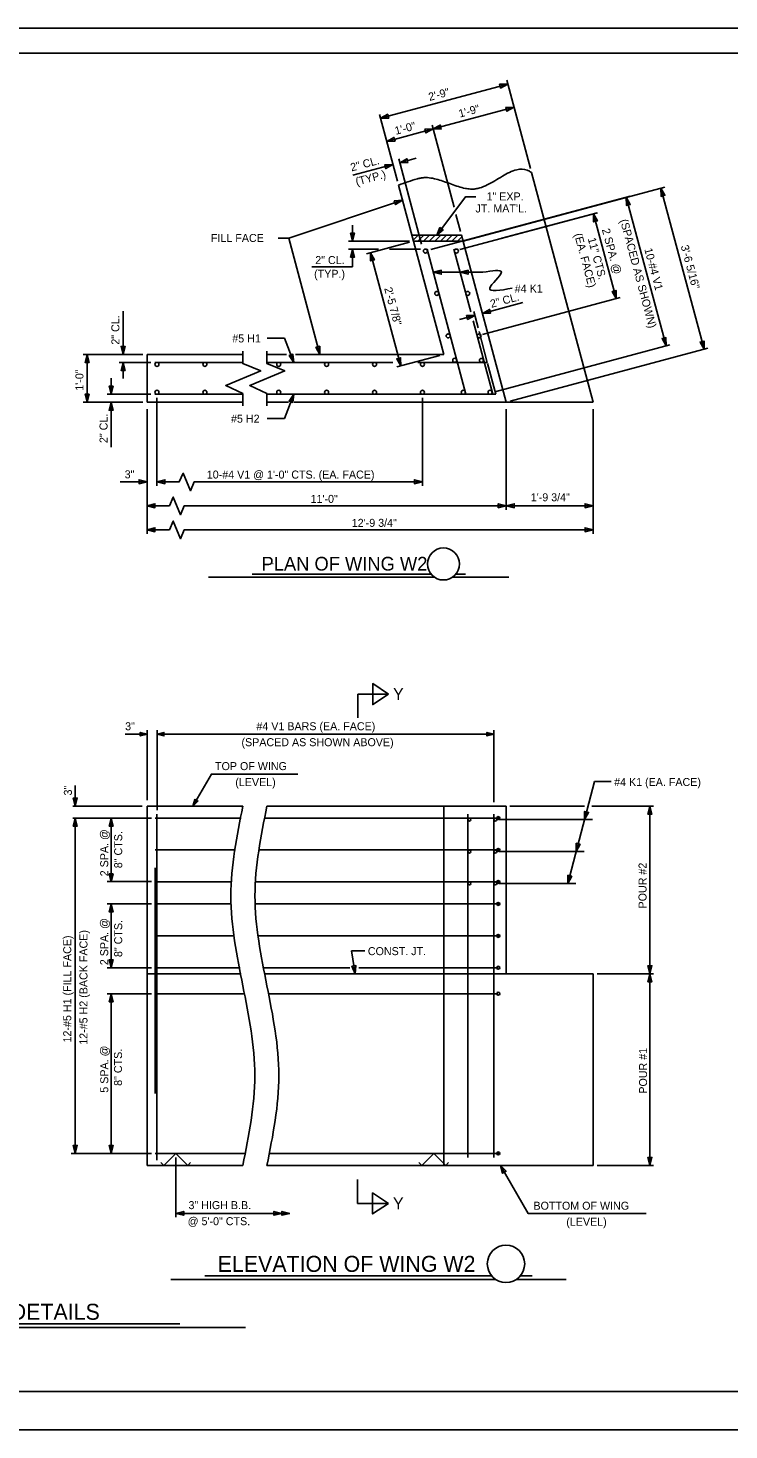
# Model space of a CAD drawing. Extents: x -41 to 191, y -168 to 6.
# Drawn here: x 18.42 to 33.05, y -98.82 to -69.56 of the extents above; entities that cross this region are included whole.
import ezdxf

# ---------------------------------------------------------------- set-up
doc = ezdxf.new("R2010")
doc.units = 0
for name, color, linetype in [('Arrowhead Terminators CELL', 7, 'Continuous'), ('Beam Bolsters CELL', 7, 'Continuous'), ('Default', 7, 'Continuous'), ('Dimension Lines', 7, 'Continuous'), ('Mis Object Lines', 7, 'Continuous'), ('Mis Object Lines Hidden', 7, 'Continuous'), ('Plan Sheet CELL', 7, 'Continuous'), ('Plot Shape CELL', 7, 'Continuous'), ('Rebar K Bar Lines', 7, 'Continuous'), ('Rebar Lines', 7, 'Continuous'), ('Sub End Bent Cap Lines', 7, 'Continuous'), ('Sub End Bent Cap Lines CELL', 7, 'Continuous'), ('Subtitle Text', 7, 'Continuous'), ('Text', 7, 'Continuous'), ('Title Text', 7, 'Continuous'), ('User Information Notes CELL', 7, 'Continuous')]:
    doc.layers.add(name, color=color, linetype=linetype)

# ---------------------------------------------------------------- blocks, each defined once
blk = doc.blocks.new('3 HIGH BEAM BOLSTER')
at = {"layer": 'Default'}
blk.add_lwpolyline([(-0.31, -0.192), (-0.251, -0.251), (0, 0), (0.251, -0.251), (0.31, -0.192)], dxfattribs=at)
blk = doc.blocks.new('SECSYM')
at = {"layer": 'Arrowhead Terminators CELL'}
blk.add_lwpolyline([(0, 0), (-2.48, 1.65), (-2.48, -1.65)], close=True, dxfattribs=at)
blk = doc.blocks.new('AH')
at = {"layer": 'Sub End Bent Cap Lines CELL'}
blk.add_lwpolyline([(0, 0), (-1.25, 0.31), (-1.25, -0.31)], close=True, dxfattribs=at)

msp = doc.modelspace()

# ---------------------------------------------------------------- linework, layer by layer
at = {"layer": 'Arrowhead Terminators CELL'}
for points in [[(28.436, -70.734), (28.265, -70.737), (28.286, -70.817)], [(25.78, -71.446), (25.951, -71.443), (25.93, -71.363)], [(28.566, -71.217), (28.394, -71.22), (28.416, -71.3)], [(26.875, -71.67), (26.704, -71.673), (26.725, -71.753)], [(26.875, -71.67), (27.047, -71.667), (27.025, -71.587)], [(25.909, -71.929), (26.081, -71.926), (26.059, -71.846)], [(26.039, -72.412), (25.867, -72.415), (25.889, -72.495)], [(26.18, -72.374), (26.352, -72.371), (26.33, -72.291)], [(30.908, -73.094), (30.911, -73.265), (30.991, -73.244)], [(31.633, -72.904), (31.636, -73.076), (31.716, -73.054)], [(26.238, -73.157), (26.067, -73.17), (26.094, -73.249)], [(30.224, -73.439), (30.227, -73.61), (30.307, -73.589)], [(26.951, -73.886), (27.085, -73.778), (27.018, -73.728)], [(25.195, -74.011), (25.237, -73.845), (25.153, -73.845)], [(25.195, -74.178), (25.153, -74.344), (25.237, -74.344)], [(25.568, -74.252), (25.571, -74.423), (25.652, -74.402)], [(26.879, -74.661), (27.045, -74.702), (27.045, -74.619)], [(27.439, -74.661), (27.606, -74.702), (27.606, -74.619)], [(30.698, -75.21), (30.695, -75.039), (30.615, -75.06)], [(27.907, -75.519), (28.078, -75.516), (28.056, -75.436)], [(27.746, -75.562), (27.574, -75.565), (27.596, -75.645)], [(31.739, -76.196), (31.736, -76.025), (31.656, -76.046)], [(24.514, -76.374), (24.511, -76.203), (24.431, -76.224)], [(32.535, -76.267), (32.532, -76.096), (32.451, -76.118)], [(23.971, -76.541), (23.95, -76.371), (23.873, -76.4)], [(26.202, -76.615), (26.199, -76.444), (26.119, -76.465)], [(23.971, -77.208), (23.95, -77.378), (23.873, -77.348)], [(20.904, -79.033), (20.737, -78.992), (20.737, -79.075)], [(21.112, -79.033), (21.279, -79.075), (21.279, -78.992)], [(26.654, -79.033), (26.487, -78.992), (26.487, -79.075)], [(20.904, -79.533), (21.07, -79.575), (21.07, -79.492)], [(28.404, -79.533), (28.237, -79.492), (28.237, -79.575)], [(28.404, -79.533), (28.57, -79.575), (28.57, -79.492)], [(30.215, -79.533), (30.049, -79.492), (30.049, -79.575)], [(20.904, -80.033), (21.07, -80.075), (21.07, -79.992)], [(30.215, -80.033), (30.049, -79.992), (30.049, -80.075)], [(20.905, -84.302), (20.763, -84.337), (20.763, -84.266)], [(21.114, -84.302), (21.256, -84.266), (21.256, -84.337)], [(28.142, -84.302), (28, -84.337), (28, -84.266)], [(19.405, -85.802), (19.447, -85.635), (19.364, -85.635)], [(21.862, -85.802), (21.965, -85.697), (21.904, -85.661)], [(30.038, -86.083), (30.04, -85.912), (30.121, -85.933)], [(31.404, -85.802), (31.362, -85.968), (31.445, -85.968)], [(19.405, -86.052), (19.364, -86.218), (19.447, -86.218)], [(20.155, -86.052), (20.114, -86.218), (20.197, -86.218)], [(29.863, -86.75), (29.865, -86.578), (29.946, -86.599)], [(20.155, -87.379), (20.197, -87.213), (20.114, -87.213)], [(29.688, -87.416), (29.69, -87.245), (29.771, -87.266)], [(20.155, -87.843), (20.114, -88.01), (20.197, -88.01)], [(20.155, -89.177), (20.197, -89.01), (20.114, -89.01)], [(25.252, -89.302), (25.183, -89.145), (25.265, -89.131)], [(31.404, -89.302), (31.445, -89.135), (31.362, -89.135)], [(31.404, -89.302), (31.362, -89.468), (31.445, -89.468)], [(20.155, -89.718), (20.114, -89.885), (20.197, -89.885)], [(19.405, -93.052), (19.447, -92.885), (19.364, -92.885)], [(20.155, -93.052), (20.197, -92.885), (20.114, -92.885)], [(28.28, -93.302), (28.399, -93.425), (28.327, -93.466)], [(31.404, -93.302), (31.445, -93.135), (31.362, -93.135)], [(21.505, -94.302), (21.671, -94.26), (21.671, -94.343)], [(23.72, -94.302), (23.554, -94.26), (23.554, -94.343)], [(23.886, -94.302), (23.72, -94.26), (23.72, -94.343)]]:
    msp.add_lwpolyline(points, close=True, dxfattribs=at)
at = {"layer": 'Beam Bolsters CELL'}
msp.add_lwpolyline([(21.814, -93.243), (21.755, -93.302), (21.505, -93.052), (21.254, -93.302), (21.195, -93.243)], dxfattribs=at)
at = {"layer": 'Default'}
for points in [[(22.904, -77.449), (22.904, -77.191), (22.546, -77.027), (23.279, -76.721), (22.904, -76.566), (22.904, -76.304)], [(23.406, -77.449), (23.406, -77.191), (23.048, -77.027), (23.781, -76.721), (23.406, -76.566), (23.406, -76.304)], [(21.449, -79.033), (21.578, -79.033), (21.66, -78.854), (21.813, -79.221), (21.891, -79.033), (22.022, -79.033)], [(21.241, -79.533), (21.37, -79.533), (21.452, -79.354), (21.605, -79.721), (21.682, -79.533), (21.813, -79.533)], [(21.241, -80.033), (21.37, -80.033), (21.452, -79.854), (21.605, -80.221), (21.682, -80.033), (21.813, -80.033)]]:
    msp.add_lwpolyline(points, dxfattribs=at)
at = {"layer": 'Dimension Lines'}
for p, q in [((25.78, -71.446), (28.436, -70.734)), ((28.908, -72.496), (28.415, -70.654)), ((26.132, -72.762), (25.758, -71.365)), ((26.875, -71.67), (28.566, -71.217)), ((25.909, -71.929), (26.875, -71.67)), ((27.313, -73.304), (26.854, -71.59)), ((25.198, -72.637), (26.039, -72.412)), ((26.636, -74.075), (26.159, -72.293)), ((26.522, -72.282), (26.18, -72.374)), ((26.831, -74.186), (30.988, -73.072)), ((27.503, -74.011), (31.714, -72.883)), ((30.908, -73.094), (31.739, -76.196)), ((31.633, -72.904), (32.535, -76.267)), ((27.431, -74.187), (30.307, -73.417)), ((28.311, -73.952), (30.304, -73.418)), ((30.224, -73.439), (30.698, -75.21)), ((25.195, -73.678), (25.195, -74.011)), ((27.449, -73.811), (27.353, -73.454)), ((26.384, -74.011), (25.112, -74.011)), ((26.462, -73.991), (26.567, -73.886)), ((26.56, -74.011), (26.685, -73.886)), ((26.678, -74.011), (26.803, -73.886)), ((26.795, -74.011), (26.92, -73.886)), ((26.913, -74.011), (27.038, -73.886)), ((27.031, -74.011), (27.156, -73.886)), ((27.149, -74.011), (27.274, -73.886)), ((27.267, -74.011), (27.392, -73.886)), ((27.385, -74.011), (27.478, -73.918)), ((25.735, -74.178), (25.112, -74.178)), ((25.195, -74.511), (25.195, -74.178)), ((26.387, -74.033), (25.488, -74.273)), ((25.568, -74.252), (26.202, -76.615)), ((26.613, -74.178), (25.966, -74.178)), ((24.344, -74.548), (25.195, -74.548)), ((25.195, -74.548), (25.195, -74.459)), ((29.427, -74.432), (29.427, -74.432)), ((27.439, -74.661), (26.879, -74.661)), ((27.915, -74.661), (27.439, -74.661)), ((27.906, -75.958), (30.779, -75.188)), ((20.404, -75.475), (20.404, -76.374)), ((27.724, -75.482), (27.814, -75.819)), ((27.907, -75.519), (28.748, -75.294)), ((27.746, -75.562), (27.424, -75.648)), ((23.414, -76.035), (23.777, -76.035)), ((23.777, -76.035), (23.971, -76.541)), ((28.162, -77.155), (31.819, -76.175)), ((28.484, -77.353), (32.615, -76.246)), ((20.82, -76.374), (19.57, -76.374)), ((19.654, -76.374), (19.654, -77.374)), ((20.987, -76.541), (20.32, -76.541)), ((20.404, -76.875), (20.404, -76.541)), ((20.82, -76.374), (20.467, -76.374)), ((27.02, -76.396), (26.121, -76.637)), ((20.154, -76.874), (20.154, -77.208)), ((20.987, -77.208), (20.07, -77.208)), ((23.777, -77.714), (23.971, -77.208)), ((20.82, -77.374), (19.57, -77.374)), ((20.154, -78.308), (20.154, -77.374)), ((20.82, -77.374), (20.178, -77.374)), ((20.904, -77.517), (20.904, -80.117)), ((21.112, -77.279), (21.112, -79.118)), ((26.654, -77.279), (26.654, -79.118)), ((28.404, -77.517), (28.404, -79.617)), ((30.215, -77.517), (30.215, -80.117)), ((23.414, -77.714), (23.777, -77.714)), ((20.341, -79.033), (20.904, -79.033)), ((21.449, -79.033), (21.112, -79.033)), ((22.022, -79.033), (26.654, -79.033)), ((21.241, -79.533), (20.904, -79.533)), ((28.404, -79.533), (21.813, -79.533)), ((30.215, -79.533), (28.404, -79.533)), ((21.241, -80.033), (20.904, -80.033)), ((30.215, -80.033), (21.813, -80.033)), ((25.302, -83.463), (25.302, -83.961)), ((25.945, -83.463), (25.302, -83.463)), ((20.905, -85.679), (20.905, -84.218)), ((21.114, -85.885), (21.114, -84.218)), ((28.142, -85.718), (28.142, -84.218)), ((20.447, -84.302), (20.905, -84.302)), ((28.142, -84.302), (21.114, -84.302)), ((19.405, -85.802), (19.405, -85.37)), ((29.688, -87.416), (30.247, -85.287)), ((30.247, -85.287), (30.592, -85.287)), ((20.802, -85.802), (19.357, -85.802)), ((28.476, -85.802), (30.038, -85.802)), ((30.189, -85.802), (31.475, -85.802)), ((31.404, -89.302), (31.404, -85.802)), ((21, -86.052), (19.357, -86.052)), ((19.405, -86.052), (19.405, -93.052)), ((20.155, -87.379), (20.155, -86.052)), ((28.258, -86.083), (30.205, -86.083)), ((28.258, -86.75), (30.03, -86.75)), ((21, -87.379), (20.072, -87.379)), ((28.258, -87.416), (29.855, -87.416)), ((21, -87.843), (20.072, -87.843)), ((20.155, -89.177), (20.155, -87.843)), ((25.252, -89.302), (25.172, -88.825)), ((25.172, -88.825), (25.453, -88.825)), ((21, -89.177), (20.072, -89.177)), ((30.301, -89.302), (31.476, -89.302)), ((31.404, -93.302), (31.404, -89.302)), ((21, -89.718), (20.072, -89.718)), ((20.155, -93.052), (20.155, -89.718)), ((21, -93.052), (19.322, -93.052)), ((21.505, -93.135), (21.505, -94.385)), ((30.301, -93.302), (31.476, -93.302)), ((25.3, -94.094), (25.3, -93.594)), ((25.944, -94.094), (25.3, -94.094)), ((25.379, -94.094), (25.944, -94.094)), ((23.886, -94.302), (21.505, -94.302))]:
    msp.add_line(p, q, dxfattribs=at)
for points in [[(27.77, -73.089), (27.551, -73.089), (26.951, -73.886)], [(26.238, -73.157), (23.864, -73.95), (23.643, -73.95)], [(23.643, -73.95), (23.864, -73.95), (24.514, -76.374)], [(24.055, -85.135), (22.247, -85.135), (21.862, -85.802)], [(31.321, -94.302), (28.858, -94.302), (28.28, -93.302)]]:
    msp.add_lwpolyline(points, dxfattribs=at)
msp.add_lwpolyline([(26.434, -73.886), (26.467, -74.011), (27.503, -74.011), (27.469, -73.886)], close=True, dxfattribs=at)
for points in [[(27.915, -74.661), (28.301, -74.661), (28.059, -74.993), (28.527, -74.993)], [(22.905, -85.802), (22.655, -87.677), (22.905, -89.552), (23.155, -91.427), (22.905, -93.302)], [(23.407, -85.802), (23.157, -87.677), (23.407, -89.552), (23.657, -91.427), (23.407, -93.302)]]:
    msp.add_spline(points, degree=3, dxfattribs=at)
at = {"layer": 'Mis Object Lines'}
for p, q in [((20.905, -85.802), (22.905, -85.802)), ((20.905, -85.802), (20.905, -93.302)), ((23.407, -85.802), (28.404, -85.802)), ((28.404, -89.302), (28.404, -85.802)), ((30.215, -89.302), (28.404, -89.302)), ((30.215, -93.302), (30.215, -89.302)), ((20.905, -93.302), (22.905, -93.302)), ((23.407, -93.302), (30.215, -93.302))]:
    msp.add_line(p, q, dxfattribs=at)
msp.add_spline([(26.154, -72.842), (26.548, -72.711), (26.618, -72.694), (26.688, -72.685), (26.829, -72.693), (27.117, -72.771), (27.406, -72.873), (27.55, -72.91), (27.658, -72.924), (27.693, -72.925), (27.732, -72.924), (27.771, -72.919), (27.849, -72.901), (28.007, -72.837), (28.323, -72.657), (28.626, -72.52), (28.839, -72.527), (28.906, -72.561), (28.93, -72.577)], degree=3, dxfattribs=at)
at = {"layer": 'Mis Object Lines Hidden'}
for p, q in [((27.1, -85.802), (27.1, -93.302)), ((22.868, -89.302), (20.905, -89.302)), ((28.404, -89.302), (23.37, -89.302))]:
    msp.add_line(p, q, dxfattribs=at)
at = {"layer": 'Plan Sheet CELL'}
for p, q in [((1.402, -70.087), (43.962, -70.087)), ((1.402, -98.017), (43.962, -98.017))]:
    msp.add_line(p, q, dxfattribs=at)
at = {"layer": 'Plot Shape CELL'}
msp.add_lwpolyline([(0, -69.563), (43.974, -69.563), (43.974, -98.823), (0, -98.823)], close=True, dxfattribs=at)
at = {"layer": 'Rebar K Bar Lines'}
for p, q in [((27.561, -77.208), (26.749, -74.178)), ((27.661, -75.489), (27.31, -74.178)), ((28.122, -77.208), (27.71, -75.673))]:
    msp.add_line(p, q, dxfattribs=at)
for centre in [(27.633, -86.083), (28.175, -86.083), (27.633, -86.75), (28.175, -86.75), (27.633, -87.416), (28.175, -87.416)]:
    msp.add_circle(centre, 0.0312, dxfattribs=at)
at = {"layer": 'Rebar Lines'}
for p, q in [((28.008, -76.541), (27.835, -75.897)), ((22.904, -76.541), (21.07, -76.541)), ((26.035, -76.541), (23.406, -76.541)), ((28.008, -76.541), (26.556, -76.541)), ((28.186, -77.208), (28.014, -76.564)), ((22.904, -77.208), (21.07, -77.208)), ((28.186, -77.208), (23.406, -77.208)), ((21.112, -85.968), (21.112, -93.189)), ((27.598, -85.968), (27.598, -93.135)), ((28.142, -85.968), (28.142, -93.135)), ((21.072, -86.052), (22.868, -86.052)), ((23.37, -86.052), (28.273, -86.052)), ((21.072, -86.718), (22.752, -86.718)), ((23.254, -86.718), (28.273, -86.718)), ((21.072, -87.385), (22.666, -87.385)), ((23.168, -87.385), (28.273, -87.385)), ((21.072, -87.843), (22.659, -87.843)), ((23.161, -87.843), (28.273, -87.843)), ((21.072, -88.51), (22.732, -88.51)), ((23.234, -88.51), (28.273, -88.51)), ((21.072, -89.177), (22.847, -89.177)), ((23.349, -89.177), (25.135, -89.177)), ((25.324, -89.177), (28.237, -89.177)), ((21.072, -89.718), (22.929, -89.718)), ((23.431, -89.718), (28.237, -89.718)), ((21.072, -93.052), (22.942, -93.052)), ((23.444, -93.052), (28.275, -93.052))]:
    msp.add_line(p, q, dxfattribs=at)
for centre, radius in [((26.716, -74.217), 0.0417), ((27.362, -74.217), 0.0417), ((26.953, -75.102), 0.0417), ((27.599, -75.102), 0.0417), ((27.191, -75.988), 0.0417), ((27.837, -75.988), 0.0417), ((21.112, -76.583), 0.0417), ((22.112, -76.583), 0.0417), ((23.654, -76.583), 0.0417), ((24.654, -76.583), 0.0417), ((25.654, -76.583), 0.0417), ((26.654, -76.583), 0.0417), ((27.327, -76.498), 0.0417), ((27.886, -76.499), 0.0417), ((21.112, -77.166), 0.0417), ((22.112, -77.166), 0.0417), ((23.654, -77.166), 0.0417), ((24.654, -77.166), 0.0417), ((25.654, -77.166), 0.0417), ((26.654, -77.166), 0.0417), ((27.506, -77.165), 0.0417), ((28.065, -77.165), 0.0417), ((28.237, -86.052), 0.0312), ((28.237, -86.718), 0.0312), ((28.237, -87.385), 0.0312), ((28.237, -87.843), 0.0312), ((28.237, -88.51), 0.0312), ((28.237, -89.177), 0.0312), ((28.237, -89.718), 0.0312), ((28.237, -93.052), 0.0312)]:
    msp.add_circle(centre, radius, dxfattribs=at)
at = {"layer": 'Sub End Bent Cap Lines'}
for p, q in [((27.1, -76.374), (26.154, -72.842)), ((30.215, -77.374), (28.93, -72.577)), ((27.503, -74.011), (26.467, -74.011)), ((28.404, -77.374), (27.505, -74.021)), ((20.904, -77.374), (20.904, -76.374)), ((22.904, -76.374), (20.904, -76.374)), ((23.813, -76.374), (23.406, -76.374)), ((27.1, -76.374), (24.002, -76.374)), ((22.904, -77.374), (20.904, -77.374)), ((23.859, -77.374), (23.406, -77.374)), ((30.215, -77.374), (23.977, -77.374))]:
    msp.add_line(p, q, dxfattribs=at)
at = {"layer": 'Title Text'}
for p, q in [((22.191, -81.021), (26.9, -81.021)), ((23.101, -80.958), (26.832, -80.958)), ((27.284, -81.021), (28.459, -81.021)), ((27.351, -80.958), (27.55, -80.958)), ((22.114, -95.607), (28.1, -95.607)), ((28.696, -95.607), (28.945, -95.607)), ((21.402, -95.681), (28.183, -95.681)), ((28.612, -95.681), (29.656, -95.681)), ((14.226, -96.681), (22.963, -96.681)), ((14.89, -96.681), (21.67, -96.681)), ((15.601, -96.607), (21.587, -96.607))]:
    msp.add_line(p, q, dxfattribs=at)
for centre, radius in [((27.092, -80.749), 0.334), ((23.537, -80.743), 0.000000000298), ((28.398, -95.356), 0.39)]:
    msp.add_circle(centre, radius, dxfattribs=at)
at = {"layer": 'User Information Notes CELL'}
msp.add_line((21.072, -87.092), (21.072, -91.802), dxfattribs=at)

# ---------------------------------------------------------------- block references
at = {"layer": 'Arrowhead Terminators CELL', "xscale": 0.1336, "yscale": -0.1336}
for p, rotation in [((20.404, -76.374), -90), ((19.654, -76.374), 90), ((20.404, -76.541), 90), ((19.654, -77.374), -90), ((20.154, -77.208), -90), ((20.154, -77.374), 90)]:
    msp.add_blockref('AH', p, dxfattribs=dict(at, rotation=rotation))
at = {"layer": 'Dimension Lines', "xscale": 0.1331292, "yscale": 0.133130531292}
for p in [(25.945, -83.463), (25.944, -94.094)]:
    msp.add_blockref('SECSYM', p, dxfattribs=at)
at = {"layer": 'Rebar Lines', "yscale": 1.00001}
msp.add_blockref('3 HIGH BEAM BOLSTER', (26.889, -93.052), dxfattribs=at)

# ---------------------------------------------------------------- texts
at = {"layer": 'Subtitle Text'}
for p in [(26.04, -83.586), (26.038, -94.218)]:
    msp.add_text('Y', height=0.25, dxfattribs=at).set_placement(p)
at = {"layer": 'Text'}
for s, height, rotation, p in [('2\'-9"', 0.167, 15, (26.803, -71.086)), ('1\'-9"', 0.167, 15, (27.434, -71.434)), ('1\'-0"', 0.167, 15, (26.1, -71.792)), ('2" CL.', 0.167, 15, (25.175, -72.557)), ('(TYP.)', 0.167, 15, (25.282, -72.854)), ('(SPACED AS SHOWN)', 0.167, 285, (30.777, -73.575)), ('(EA. FACE)', 0.167, 285, (29.82, -73.869)), ('11" CTS.', 0.167, 285, (30.104, -73.959)), ('2 SPA. @', 0.167, 285, (30.398, -73.769)), ('2" CL.', 0.167, 0, (24.416, -74.489)), ('10-#4 V1', 0.167, 285, (31.284, -74.178)), ('3\'-6 5/16"', 0.167, 285, (32.044, -74.115)), ('(TYP.)', 0.167, 360, (24.392, -74.776)), ('2\'-5 7/8"', 0.1667, 285, (25.854, -74.997)), ('2" CL.', 0.167, 15, (28.094, -75.404)), ('2" CL.', 0.167, 90, (20.327, -76.172)), ('1\'-0"', 0.167, 90, (19.577, -77.133)), ('2" CL.', 0.167, 90, (20.08, -78.225)), ('10-#4 V1 @ 1\'-0" CTS. (EA. FACE)', 0.167, 360, (22.152, -78.966)), ('11\'-0"', 0.167, 360, (24.318, -79.474)), ('12\'-9 3/4"', 0.167, 360, (25.178, -79.974)), ('3"', 0.167, 90, (19.336, -85.58)), ('2 SPA. @', 0.167, 90, (20.094, -87.267)), ('8" CTS.', 0.167, 90, (20.386, -87.099)), ('POUR #2', 0.167, 90, (31.332, -87.939)), ('2 SPA. @', 0.167, 90, (20.094, -89.122)), ('8" CTS.', 0.167, 90, (20.386, -88.953)), ('12-#5 H1 (FILL FACE)', 0.167, 90, (19.322, -90.736)), ('12-#5 H2 (BACK FACE)', 0.167, 90, (19.661, -90.784)), ('CONST. JT.', 0.167, 360, (25.514, -88.913)), ('5 SPA. @', 0.167, 90, (20.095, -91.784)), ('8" CTS.', 0.167, 90, (20.382, -91.641)), ('POUR #1', 0.167, 90, (31.343, -91.804))]:
    msp.add_text(s, height=height, rotation=rotation, dxfattribs=at).set_placement(p)
for s, height, p in [('1" EXP.', 0.167, (27.992, -73.161)), ("JT. MAT'L.", 0.167, (27.762, -73.412)), ('FILL FACE', 0.167, (22.238, -74.028)), ('#4 K1', 0.167, (28.581, -75.083)), ('#5 H1', 0.167, (22.684, -76.125)), ('#5 H2', 0.167, (22.658, -77.8)), ('3"', 0.1667, (20.437, -78.961)), ('1\'-9 3/4"', 0.1667, (28.915, -79.44)), ('3"', 0.167, (20.447, -84.219)), ('#4 V1 BARS (EA. FACE)', 0.167, (23.188, -84.219)), ('(SPACED AS SHOWN ABOVE)', 0.167, (22.876, -84.552)), ('TOP OF WING', 0.167, (22.324, -85.051)), ('(LEVEL)', 0.167, (22.747, -85.386)), ('#4 K1 (EA. FACE)', 0.167, (30.656, -85.383)), ('3" HIGH B.B.', 0.167, (21.77, -94.214)), ('BOTTOM OF WING', 0.167, (28.971, -94.226)), ('@ 5\'-0" CTS.', 0.167, (21.753, -94.549)), ('(LEVEL)', 0.167, (29.657, -94.561))]:
    msp.add_text(s, height=height, dxfattribs=at).set_placement(p)
at = {"layer": 'Title Text'}
msp.add_text('PLAN OF WING W2', height=0.2859, rotation=360, dxfattribs=at).set_placement((23.295, -80.886))
for s, p in [('ELEVATION OF WING W2', (22.378, -95.523)), ('WING DETAILS', (16.719, -96.523))]:
    msp.add_text(s, height=0.33388, dxfattribs=at).set_placement(p)

doc.saveas('drawing.dxf')
